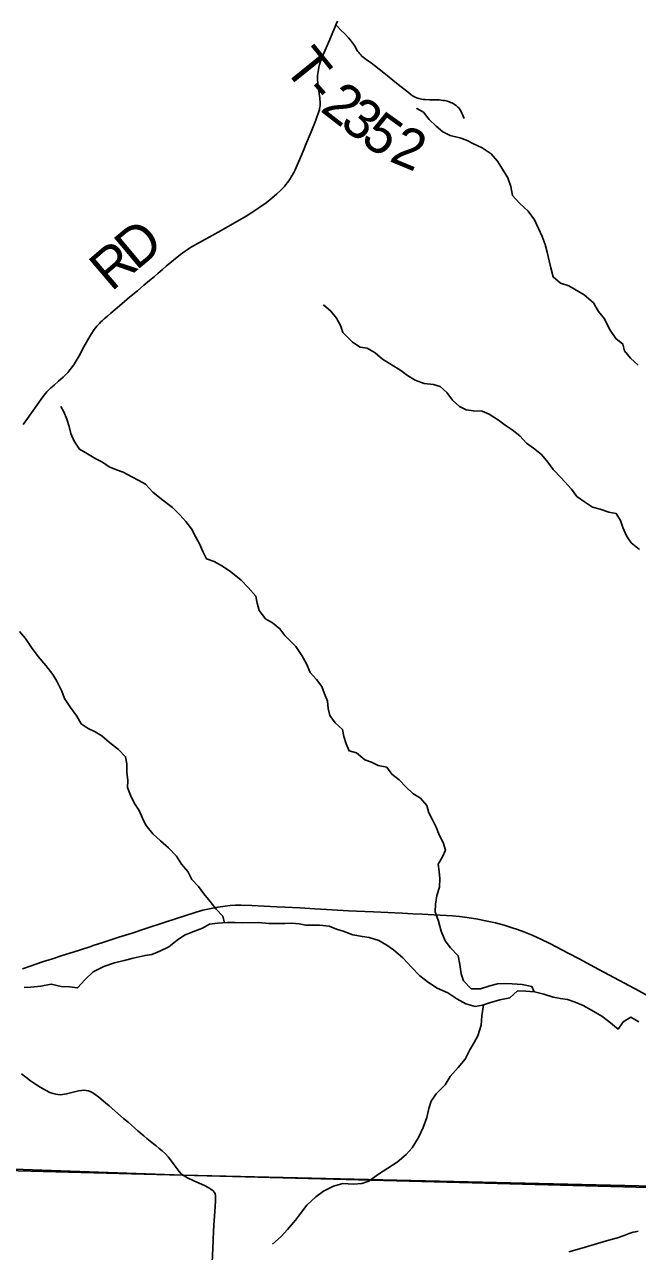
# Model space of a CAD drawing. Extents: x 0 to 34, y 0 to 22.
# Drawn here: x 4.413 to 5.288, y 17.521 to 19.271 of the extents above; entities that cross this region are included whole.
import ezdxf

# ---------------------------------------------------------------- set-up
doc = ezdxf.new("R2010")
doc.units = 0
for name, color, linetype in [('GM_X_Corporation', 7, 'Continuous'), ('GM_X_Minor_River', 7, 'Continuous'), ('GM_X_State_Route', 7, 'Continuous'), ('GM_X_Township_Road', 7, 'Continuous'), ('GM_X_Township_Road_Text', 7, 'Continuous')]:
    doc.layers.add(name, color=color, linetype=linetype)

msp = doc.modelspace()

# ---------------------------------------------------------------- linework, layer by layer
at = {"layer": 'GM_X_Corporation'}
for points in [[(5.3543, 16.3597), (5.3699, 17.5116), (5.3717, 17.6123), (4.6401, 17.6298), (4.3705, 17.6391), (4.3669, 17.8198), (4.37, 17.9048), (4.3768, 18.4091), (4.3782, 18.6502), (4.377, 18.6713), (3.7035, 18.69), (3.3642, 18.7005), (3.3691, 19.5041), (3.3724, 19.7263), (3.3869, 20.7918), (3.3886, 20.9), (2.1, 20.9), (2.1, 15.6606)], [(3.3691, 19.5041), (3.3642, 18.7005), (3.7035, 18.69), (4.377, 18.6713), (4.3782, 18.6502), (4.3768, 18.4091), (4.37, 17.9048), (4.3669, 17.8198), (4.3705, 17.6391), (4.6401, 17.6298), (5.3717, 17.6123), (5.3798, 17.8448), (5.3967, 19.0299), (5.4062, 19.5263)], [(4.3565, 17.0622), (4.3675, 17.6365), (5.3765, 17.6099), (5.3761, 17.5925), (5.36, 16.5874), (4.3481, 16.6188), (4.352, 16.8239)]]:
    msp.add_lwpolyline(points, dxfattribs=at)
at = {"layer": 'GM_X_Minor_River'}
for points in [[(5.2893, 18.785), (5.2782, 18.7951), (5.2698, 18.8053), (5.2674, 18.8151), (5.2572, 18.823), (5.2484, 18.8365), (5.241, 18.8512), (5.2326, 18.8617), (5.2254, 18.8738), (5.212, 18.8854), (5.19, 18.898), (5.1782, 18.9021), (5.1679, 18.911), (5.1644, 18.9239), (5.1621, 18.9337), (5.1593, 18.9462), (5.1566, 18.9571), (5.1519, 18.9688), (5.1469, 18.9798), (5.1412, 18.9922), (5.132, 19.0046), (5.1198, 19.0162), (5.1099, 19.0271), (5.1075, 19.04), (5.1032, 19.0524), (5.0955, 19.0645), (5.0883, 19.0758), (5.0791, 19.0863), (5.0665, 19.0949), (5.054, 19.1008), (5.0441, 19.106), (5.0347, 19.1093), (5.021, 19.1126), (5.0104, 19.1178), (5.0009, 19.126), (4.9906, 19.1354), (4.9826, 19.1459), (4.9731, 19.1511), (4.9742, 19.15)], [(5.2912, 18.5221), (5.2794, 18.5315), (5.2725, 18.5416), (5.2675, 18.5533), (5.264, 18.5635), (5.2578, 18.5733), (5.2472, 18.5755), (5.2347, 18.5795), (5.2241, 18.5824), (5.2127, 18.5899), (5.2017, 18.5977), (5.194, 18.6082), (5.1791, 18.6244), (5.1677, 18.6364), (5.1604, 18.6465), (5.1512, 18.6578), (5.1398, 18.6664), (5.1299, 18.6739), (5.1204, 18.684), (5.1094, 18.6926), (5.0995, 18.6993), (5.0896, 18.7064), (5.0763, 18.715), (5.0664, 18.7194), (5.0539, 18.7197), (5.0437, 18.7215), (5.0342, 18.7263), (5.0243, 18.7349), (5.0159, 18.7458), (5.0064, 18.7544), (4.9969, 18.7573), (4.9837, 18.7587), (4.9708, 18.7635), (4.9601, 18.7702), (4.9502, 18.7773), (4.9366, 18.7859), (4.9244, 18.7937), (4.9137, 18.8027), (4.9023, 18.8094), (4.8925, 18.8108), (4.8815, 18.8179), (4.8674, 18.8314), (4.8642, 18.8416), (4.8585, 18.8521), (4.8505, 18.8619), (4.8398, 18.8709), (4.8398, 18.8712)], [(5.0057, 18.0405), (5.0061, 18.0527), (5.0052, 18.0626), (5.0036, 18.0732), (5.01, 18.0835), (5.014, 18.0934), (5.0109, 18.1043), (5.0051, 18.1149), (5.0009, 18.1258), (4.9955, 18.1364), (4.9905, 18.1465), (4.9874, 18.1571), (4.9786, 18.1673), (4.9676, 18.174), (4.9577, 18.1833), (4.9481, 18.1935), (4.9375, 18.2017), (4.9302, 18.2115), (4.9181, 18.214), (4.9086, 18.2188), (4.8991, 18.2221), (4.8869, 18.2318), (4.8767, 18.2348), (4.8721, 18.2449), (4.869, 18.2555), (4.867, 18.2653), (4.8567, 18.2747), (4.8491, 18.2852), (4.8467, 18.2954), (4.8455, 18.3057), (4.8416, 18.3162), (4.8377, 18.3268), (4.8301, 18.3366), (4.8209, 18.3467), (4.8159, 18.3591), (4.809, 18.3708), (4.8006, 18.3836), (4.7849, 18.3994), (4.7777, 18.4091), (4.7674, 18.4174), (4.7571, 18.4233), (4.7483, 18.435), (4.7452, 18.4455), (4.7432, 18.4557), (4.7325, 18.4681), (4.7226, 18.4783), (4.7078, 18.4902), (4.696, 18.4981), (4.6838, 18.5048), (4.6728, 18.5088), (4.6678, 18.5194), (4.6636, 18.5292), (4.6571, 18.5408), (4.6517, 18.5514), (4.6436, 18.5619), (4.6349, 18.5717), (4.6246, 18.5822), (4.6086, 18.5941), (4.5964, 18.6039), (4.5857, 18.6155), (4.5762, 18.6203), (4.5664, 18.6259), (4.5542, 18.6322), (4.5443, 18.6359), (4.5341, 18.64), (4.5246, 18.6467), (4.5151, 18.6515), (4.5029, 18.6586), (4.4915, 18.6653), (4.4839, 18.6766), (4.4793, 18.6875), (4.4769, 18.6977), (4.4734, 18.7079), (4.4695, 18.7185), (4.4649, 18.726)], [(4.6988, 17.9896), (4.6962, 17.9991), (4.6866, 18.0092), (4.6782, 18.0198), (4.6691, 18.031), (4.6614, 18.0412), (4.6519, 18.0513), (4.6465, 18.0626), (4.6373, 18.0731), (4.63, 18.0844), (4.6186, 18.0964), (4.6072, 18.1065), (4.5965, 18.1163), (4.5862, 18.129), (4.5816, 18.1388), (4.5769, 18.1498), (4.5704, 18.1596), (4.5646, 18.1716), (4.5604, 18.1826), (4.5607, 18.1924), (4.5594, 18.2045), (4.5593, 18.2163), (4.5574, 18.2265), (4.5474, 18.2366), (4.5345, 18.2467), (4.5235, 18.2564), (4.514, 18.262), (4.5041, 18.2668), (4.4938, 18.2736), (4.4877, 18.2841), (4.4789, 18.2969), (4.4704, 18.3093), (4.4666, 18.3202), (4.4593, 18.3342), (4.4535, 18.344), (4.4436, 18.3568), (4.4325, 18.3695), (4.4233, 18.3823), (4.4145, 18.3951), (4.4061, 18.4052)], [(5.1405, 17.891), (5.1375, 17.8985), (5.1235, 17.9018), (5.1095, 17.9025), (5.1, 17.9031), (5.0886, 17.9027), (5.0776, 17.8996), (5.064, 17.8956), (5.0508, 17.8952), (5.0397, 17.9068), (5.0366, 17.9167), (5.0346, 17.9303), (5.0322, 17.9424), (5.0215, 17.9541), (5.0135, 17.9639), (5.0081, 17.9775), (5.0042, 17.9919), (4.9995, 18.0052), (4.9998, 18.0162), (5.002, 18.0287), (5.0057, 18.0405)], [(5.2899, 17.8485), (5.2785, 17.8549), (5.2679, 17.8483), (5.2604, 17.838), (5.2471, 17.8489), (5.2375, 17.8564), (5.2227, 17.865), (5.2105, 17.8714), (5.1991, 17.8766), (5.1885, 17.88), (5.1782, 17.8814), (5.168, 17.8836), (5.1547, 17.8877), (5.1414, 17.891), (5.1289, 17.892), (5.1167, 17.8923), (5.1062, 17.8827), (5.0918, 17.8799), (5.0771, 17.8753), (5.0668, 17.8721), (5.0566, 17.8702), (5.0433, 17.8742), (5.0304, 17.8813), (5.0174, 17.8896), (5.0022, 17.8963), (4.9897, 17.9042), (4.9775, 17.9139), (4.9656, 17.9264), (4.953, 17.9395), (4.94, 17.9508), (4.9305, 17.9579), (4.9191, 17.9643), (4.905, 17.9684), (4.8955, 17.9698), (4.8819, 17.9724), (4.8682, 17.9776), (4.8583, 17.9805), (4.848, 17.985), (4.8344, 17.9864), (4.8147, 17.9862), (4.8052, 17.9881), (4.7949, 17.9891), (4.7847, 17.9886), (4.7745, 17.9886), (4.762, 17.9888), (4.7472, 17.9899), (4.7244, 17.9897), (4.7134, 17.99), (4.7028, 17.9899), (4.6888, 17.989), (4.6771, 17.9874), (4.6672, 17.982), (4.6533, 17.9766), (4.6415, 17.9719), (4.6313, 17.965), (4.6193, 17.9554), (4.6061, 17.9493), (4.5951, 17.9443), (4.5853, 17.943), (4.5682, 17.9391), (4.5554, 17.936), (4.5417, 17.9324), (4.5266, 17.9274), (4.5111, 17.9197), (4.4998, 17.9086), (4.4889, 17.8967), (4.4775, 17.8981), (4.4654, 17.8988), (4.4513, 17.9021), (4.4366, 17.8993), (4.4222, 17.8977), (4.4127, 17.8973)], [(5.0686, 17.8727), (5.0662, 17.857), (5.0651, 17.8437), (5.0603, 17.8285), (5.0551, 17.8189), (5.0491, 17.8083), (5.042, 17.7949), (5.0322, 17.7831), (5.0206, 17.7701), (5.0138, 17.7583), (5.0006, 17.7456), (4.9939, 17.7353), (4.9902, 17.7247), (4.9876, 17.7118), (4.9824, 17.6977), (4.9757, 17.6832), (4.9667, 17.6687), (4.958, 17.6592), (4.9452, 17.648), (4.932, 17.6396), (4.9184, 17.6311), (4.9045, 17.6212), (4.8947, 17.6177), (4.8829, 17.6168), (4.8677, 17.6178), (4.8541, 17.6139), (4.8398, 17.6066), (4.8288, 17.5989), (4.8164, 17.5867), (4.807, 17.5748), (4.7999, 17.5653), (4.7886, 17.5519), (4.7796, 17.542), (4.7671, 17.5313)]]:
    msp.add_lwpolyline(points, dxfattribs=at)
at = {"layer": 'GM_X_State_Route'}
msp.add_lwpolyline([(4.4105, 17.9239), (4.421, 17.9277), (4.4387, 17.9337), (4.4529, 17.9382), (4.4671, 17.9427), (4.4825, 17.9475), (4.5049, 17.9549), (4.5078, 17.9559), (4.5112, 17.9571), (4.5248, 17.9616), (4.5479, 17.9689), (4.5667, 17.9748), (4.5836, 17.9803), (4.6154, 17.9911), (4.642, 17.9997), (4.658, 18.0046), (4.6676, 18.0074), (4.6798, 18.0102), (4.6896, 18.0121), (4.6995, 18.0135), (4.7069, 18.0142), (4.7144, 18.0146), (4.7225, 18.0147), (4.7375, 18.0144), (4.7555, 18.0135), (4.7735, 18.0124), (4.7846, 18.0118), (4.8064, 18.0109), (4.8275, 18.0097), (4.8523, 18.0082), (4.8758, 18.0068), (4.887, 18.0062), (4.9112, 18.0054), (4.9522, 18.0032), (4.9677, 18.0026), (4.9807, 18.0019), (4.9974, 18.0011), (5.0154, 18.0002), (5.0241, 17.9995), (5.034, 17.9985), (5.0451, 17.997), (5.0605, 17.9946), (5.0714, 17.9925), (5.0854, 17.9893), (5.098, 17.986), (5.1094, 17.9826), (5.117, 17.98), (5.1258, 17.9767), (5.1379, 17.9717), (5.1504, 17.9661), (5.1632, 17.9599), (5.1902, 17.9459), (5.205, 17.938), (5.2269, 17.9263), (5.2471, 17.9153), (5.2838, 17.8957), (5.3321, 17.8699)], dxfattribs=at)
at = {"layer": 'GM_X_Township_Road'}
msp.add_line((4.8576, 19.2704), (4.8599, 19.2758), dxfattribs=at)
for points in [[(4.4114, 18.7005), (4.4174, 18.7091), (4.4231, 18.7169), (4.4312, 18.7284), (4.4394, 18.7399), (4.4412, 18.7424), (4.443, 18.7447), (4.445, 18.747), (4.447, 18.749), (4.4506, 18.7525), (4.4553, 18.7566), (4.4619, 18.7622), (4.4684, 18.768), (4.4727, 18.7723), (4.4748, 18.7746), (4.4766, 18.7766), (4.4783, 18.7787), (4.4799, 18.7807), (4.4816, 18.7829), (4.4835, 18.7856), (4.4854, 18.7887), (4.487, 18.7913), (4.4911, 18.7984), (4.4979, 18.8113), (4.5034, 18.8211), (4.5082, 18.8291), (4.5127, 18.8359), (4.5147, 18.8385), (4.5163, 18.8407), (4.5181, 18.8426), (4.52, 18.8447), (4.522, 18.8467), (4.5244, 18.8489), (4.5268, 18.851), (4.5314, 18.855), (4.5365, 18.8594), (4.552, 18.8727), (4.5629, 18.8818), (4.5744, 18.8912), (4.5837, 18.8991), (4.5916, 18.9057), (4.5986, 18.9117), (4.6033, 18.9156), (4.6103, 18.9217), (4.6155, 18.9262), (4.626, 18.9349), (4.6358, 18.9427), (4.6423, 18.9475), (4.6452, 18.9495), (4.6485, 18.9517), (4.6534, 18.9546), (4.6587, 18.9577), (4.6896, 18.9749), (4.7172, 18.9905), (4.7294, 18.9976), (4.7378, 19.0029), (4.749, 19.0104), (4.758, 19.0168), (4.7663, 19.0232), (4.7734, 19.0292), (4.7792, 19.0347), (4.7842, 19.0401), (4.7863, 19.0426), (4.7885, 19.0454), (4.7903, 19.048), (4.7923, 19.0509), (4.7939, 19.0536), (4.7958, 19.0567), (4.7975, 19.0597), (4.7994, 19.0637), (4.8025, 19.0704), (4.8071, 19.0812), (4.8122, 19.0938), (4.8144, 19.0989), (4.8223, 19.1177), (4.8289, 19.1344), (4.8311, 19.1403), (4.8324, 19.144), (4.8334, 19.1468), (4.8341, 19.1493), (4.8345, 19.1513), (4.8349, 19.1531), (4.8351, 19.1548), (4.8352, 19.1568), (4.8352, 19.1587), (4.8351, 19.161), (4.8349, 19.1636), (4.8346, 19.1663), (4.8327, 19.1785), (4.8318, 19.1866), (4.8315, 19.1928), (4.8315, 19.1956), (4.8316, 19.1983), (4.8318, 19.2011), (4.8322, 19.2041), (4.8327, 19.207), (4.8335, 19.2102), (4.8344, 19.2137), (4.8354, 19.2169), (4.8366, 19.2204), (4.8382, 19.2245), (4.8439, 19.2376), (4.8491, 19.2496), (4.8531, 19.2599), (4.856, 19.2666), (4.8576, 19.2704)], [(4.8576, 19.2704), (4.86, 19.2679), (4.8642, 19.2636), (4.8707, 19.2572), (4.8756, 19.2518), (4.8784, 19.2484), (4.8814, 19.2448), (4.8827, 19.243), (4.8845, 19.2402), (4.8882, 19.2339), (4.8891, 19.2324), (4.8903, 19.2308), (4.8918, 19.2291), (4.8932, 19.2276), (4.8948, 19.226), (4.8968, 19.2242), (4.9012, 19.2208), (4.9079, 19.2163), (4.913, 19.2126), (4.926, 19.2022), (4.9468, 19.1854), (4.9613, 19.1738), (4.9652, 19.1708), (4.9667, 19.1698), (4.9689, 19.1685), (4.9728, 19.1666), (4.9745, 19.1659), (4.9763, 19.1653), (4.9799, 19.1645), (4.9823, 19.1642), (4.9849, 19.1639), (4.9917, 19.1635), (5.0053, 19.1633), (5.0081, 19.1631), (5.0109, 19.1628), (5.0128, 19.1625), (5.0151, 19.162), (5.0172, 19.1614), (5.0193, 19.1607), (5.0213, 19.1599), (5.0233, 19.1591), (5.025, 19.1582), (5.0266, 19.1573), (5.0286, 19.156), (5.0296, 19.1552), (5.0319, 19.1531), (5.033, 19.1519), (5.0339, 19.1508), (5.0358, 19.1476), (5.0394, 19.1404), (5.041, 19.1371)], [(4.6403, 17.6292), (4.637, 17.6317), (4.634, 17.6347), (4.6309, 17.6385), (4.6256, 17.6461), (4.6216, 17.6516), (4.6181, 17.6559), (4.6142, 17.6599), (4.6097, 17.6641), (4.6054, 17.6677), (4.6011, 17.6713), (4.5972, 17.6743), (4.5876, 17.6821), (4.5834, 17.6857), (4.5782, 17.6901), (4.5749, 17.6929), (4.5609, 17.7052), (4.5547, 17.7105), (4.5342, 17.7285), (4.529, 17.733), (4.5193, 17.7407), (4.5139, 17.7447), (4.5108, 17.7468), (4.5076, 17.7486), (4.5047, 17.7497), (4.5011, 17.7504), (4.498, 17.7506), (4.4943, 17.7504), (4.49, 17.7497), (4.4809, 17.7475), (4.4731, 17.7456), (4.4676, 17.7447), (4.4639, 17.7444), (4.4608, 17.7445), (4.4577, 17.745), (4.4541, 17.7459), (4.4495, 17.7477), (4.4433, 17.7507), (4.4357, 17.7549), (4.4289, 17.7592), (4.4217, 17.7641), (4.4148, 17.7692), (4.4087, 17.7743)], [(4.6799, 17.4662), (4.6797, 17.4678), (4.6796, 17.4721), (4.6797, 17.4777), (4.6806, 17.4945), (4.6823, 17.5361), (4.683, 17.551), (4.6834, 17.5565), (4.6834, 17.5584), (4.6849, 17.5776), (4.686, 17.5923), (4.686, 17.5965), (4.6857, 17.6003), (4.6851, 17.6032), (4.6839, 17.6055), (4.6823, 17.6072), (4.6793, 17.6096), (4.6761, 17.6117), (4.67, 17.6148), (4.6547, 17.6215), (4.6458, 17.626), (4.6409, 17.6288), (4.6403, 17.6292)], [(5.1901, 17.5201), (5.2086, 17.5255), (5.2311, 17.5322), (5.2394, 17.5347), (5.2507, 17.5378), (5.2596, 17.5403), (5.269, 17.5435), (5.2764, 17.5462), (5.2822, 17.5481), (5.2852, 17.5489), (5.2892, 17.5498)]]:
    msp.add_lwpolyline(points, dxfattribs=at)

# ---------------------------------------------------------------- texts
at = {"layer": 'GM_X_Township_Road_Text'}
for s, rotation, p in [('T', 308.882, (4.7816, 19.2093)), ('-', 311.2178, (4.8099, 19.1742)), ('2', 322.1268, (4.8338, 19.1486)), ('3', 321.8717, (4.8614, 19.1272)), ('5', 324.342, (4.8911, 19.104)), ('2', 337.6683, (4.9321, 19.0766)), ('D', 39.9436, (4.5726, 18.9191)), ('R', 40.5287, (4.5372, 18.8889))]:
    msp.add_text(s, height=0.0568, rotation=rotation, dxfattribs=at).set_placement(p)

doc.saveas('drawing.dxf')
